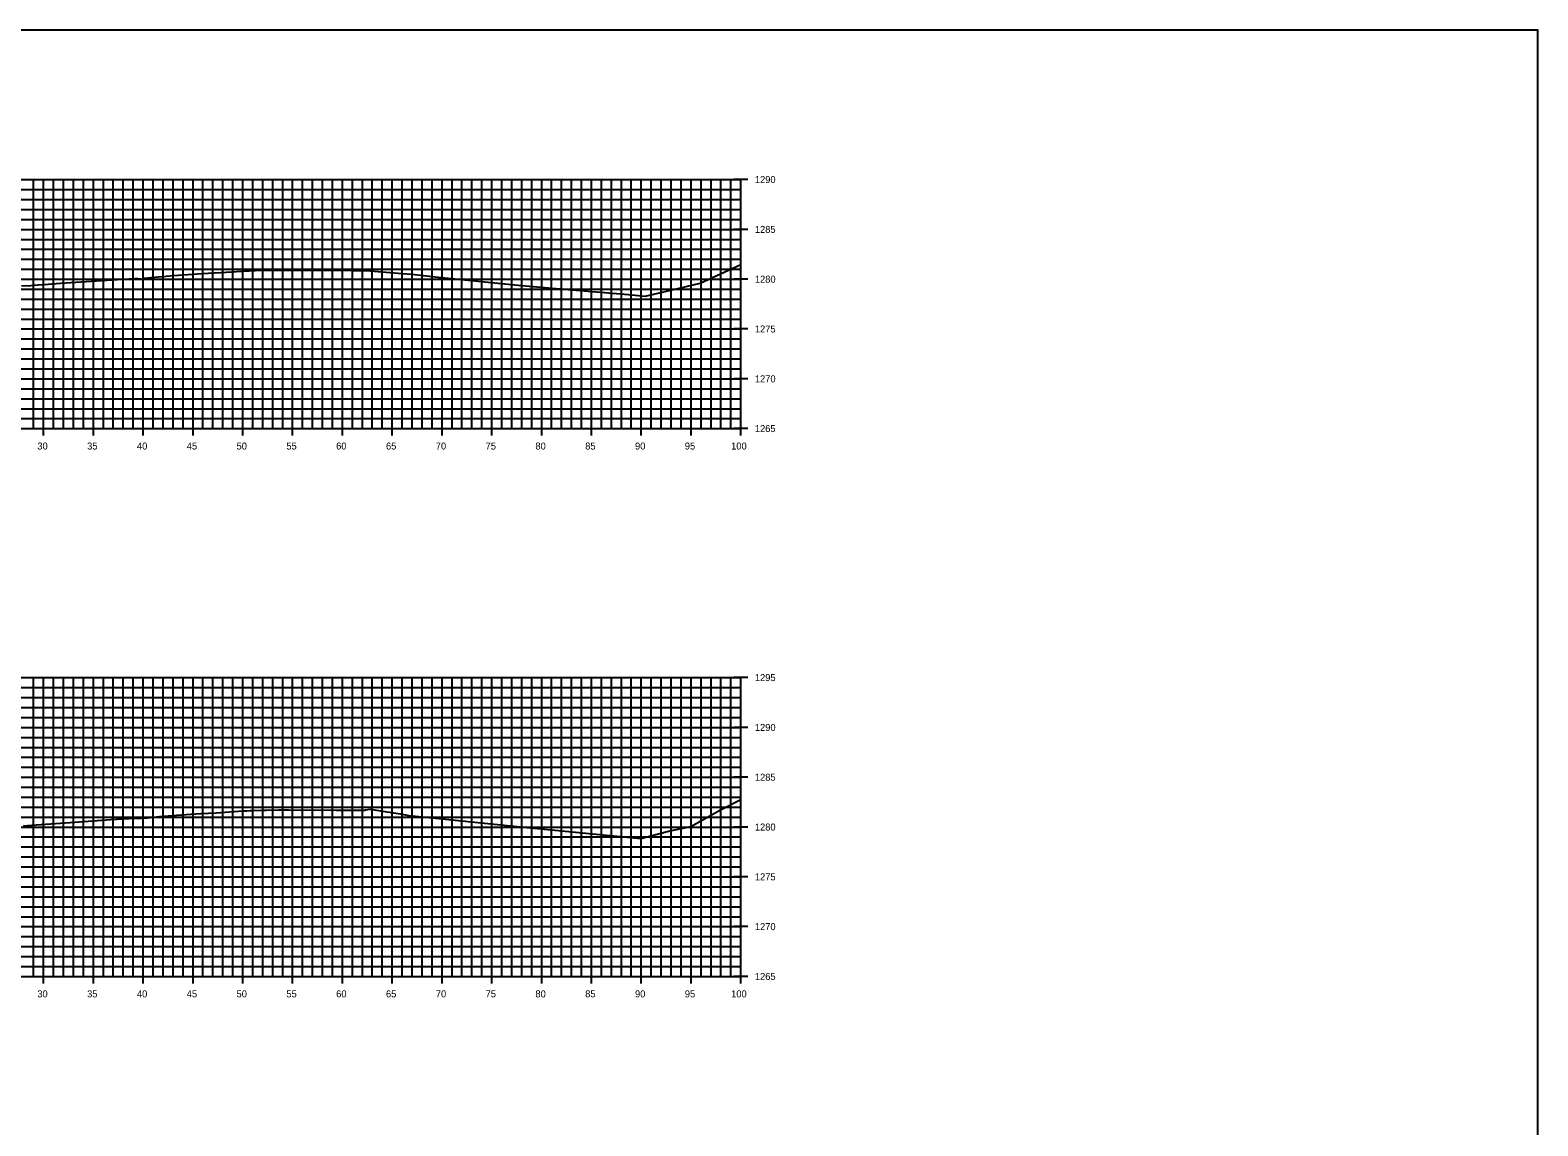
# Model space of a CAD drawing. Extents: x 674939 to 678919, y 750652 to 765176.
# Drawn here: x 678767.2 to 678918.5, y 756092.6 to 756202.6 of the extents above; entities that cross this region are included whole.
import ezdxf

# ---------------------------------------------------------------- set-up
doc = ezdxf.new("R2010")
doc.units = 0
for name, color, linetype in [('R_Axis', 7, 'Continuous'), ('R_Axis Annot', 7, 'Continuous'), ('R_Exist Surface', 7, 'Continuous'), ('R_Grid', 7, 'Continuous'), ('R_No Plot', 7, 'Continuous')]:
    doc.layers.add(name, color=color, linetype=linetype)

msp = doc.modelspace()

# ---------------------------------------------------------------- linework, layer by layer
at = {"layer": 'R_Axis'}
for p, q in [((678839.23, 756187.55), (678837.83, 756187.55)), ((678838.53, 756162.55), (678838.53, 756187.55)), ((678839.23, 756182.55), (678837.83, 756182.55)), ((678839.23, 756177.55), (678837.83, 756177.55)), ((678839.23, 756172.55), (678837.83, 756172.55)), ((678839.23, 756167.55), (678837.83, 756167.55)), ((678768.53, 756161.85), (678768.53, 756163.25)), ((678773.53, 756161.85), (678773.53, 756163.25)), ((678778.53, 756161.85), (678778.53, 756163.25)), ((678783.53, 756161.85), (678783.53, 756163.25)), ((678788.53, 756161.85), (678788.53, 756163.25)), ((678793.53, 756161.85), (678793.53, 756163.25)), ((678798.53, 756161.85), (678798.53, 756163.25)), ((678803.53, 756161.85), (678803.53, 756163.25)), ((678808.53, 756161.85), (678808.53, 756163.25)), ((678813.53, 756161.85), (678813.53, 756163.25)), ((678818.53, 756161.85), (678818.53, 756163.25)), ((678823.53, 756161.85), (678823.53, 756163.25)), ((678828.53, 756161.85), (678828.53, 756163.25)), ((678833.53, 756161.85), (678833.53, 756163.25)), ((678838.53, 756161.85), (678838.53, 756163.25)), ((678638.53, 756162.55), (678838.53, 756162.55)), ((678839.23, 756162.55), (678837.83, 756162.55)), ((678839.23, 756137.55), (678837.83, 756137.55)), ((678838.53, 756107.55), (678838.53, 756137.55)), ((678839.23, 756132.55), (678837.83, 756132.55)), ((678839.23, 756127.55), (678837.83, 756127.55)), ((678839.23, 756122.55), (678837.83, 756122.55)), ((678839.23, 756117.55), (678837.83, 756117.55)), ((678839.23, 756112.55), (678837.83, 756112.55)), ((678638.53, 756107.55), (678838.53, 756107.55)), ((678768.53, 756106.85), (678768.53, 756108.25)), ((678773.53, 756106.85), (678773.53, 756108.25)), ((678778.53, 756106.85), (678778.53, 756108.25)), ((678783.53, 756106.85), (678783.53, 756108.25)), ((678788.53, 756106.85), (678788.53, 756108.25)), ((678793.53, 756106.85), (678793.53, 756108.25)), ((678798.53, 756106.85), (678798.53, 756108.25)), ((678803.53, 756106.85), (678803.53, 756108.25)), ((678808.53, 756106.85), (678808.53, 756108.25)), ((678813.53, 756106.85), (678813.53, 756108.25)), ((678818.53, 756106.85), (678818.53, 756108.25)), ((678823.53, 756106.85), (678823.53, 756108.25)), ((678828.53, 756106.85), (678828.53, 756108.25)), ((678833.53, 756106.85), (678833.53, 756108.25)), ((678839.23, 756107.55), (678837.83, 756107.55)), ((678838.53, 756106.85), (678838.53, 756108.25))]:
    msp.add_line(p, q, dxfattribs=at)
at = {"layer": 'R_Exist Surface'}
for points in [[(678766.31, 756176.88), (678767.24, 756176.93), (678768, 756176.98), (678768.99, 756177.06), (678769.37, 756177.09), (678770.24, 756177.15), (678772.3, 756177.29), (678775.38, 756177.47), (678776.47, 756177.54), (678777.69, 756177.61), (678778, 756177.61), (678778.25, 756177.6), (678778.37, 756177.56), (678778.61, 756177.65), (678779.32, 756177.72), (678780.05, 756177.8), (678781.62, 756177.91), (678784.41, 756178.11), (678786.33, 756178.22), (678788.97, 756178.38), (678789.18, 756178.39), (678789.53, 756178.41), (678789.64, 756178.42), (678789.77, 756178.43), (678790.72, 756178.44), (678792.27, 756178.44), (678795.68, 756178.44), (678797.33, 756178.44), (678797.67, 756178.44), (678799.65, 756178.42), (678800.65, 756178.41), (678800.69, 756178.42), (678800.92, 756178.43), (678804.51, 756178.12), (678805.5, 756178.04), (678808.14, 756177.75), (678816.49, 756176.92), (678820, 756176.6), (678827.26, 756176.01), (678828.93, 756175.84), (678830.79, 756176.27), (678834.44, 756177.16), (678838.53, 756179.02)], [(678766.49, 756122.67), (678767.8, 756122.78), (678771.19, 756123.01), (678775.29, 756123.29), (678777.72, 756123.45), (678778.09, 756123.44), (678778.32, 756123.43), (678778.95, 756123.49), (678780.17, 756123.6), (678781.87, 756123.73), (678784.32, 756123.9), (678785.86, 756123.99), (678788.57, 756124.16), (678788.92, 756124.18), (678789.31, 756124.21), (678789.41, 756124.21), (678789.52, 756124.22), (678790.39, 756124.23), (678790.92, 756124.23), (678792.16, 756124.26), (678793.15, 756124.26), (678797.87, 756124.25), (678800.52, 756124.23), (678800.77, 756124.25), (678800.85, 756124.26), (678801.09, 756124.3), (678801.3, 756124.34), (678804.32, 756123.86), (678805.18, 756123.72), (678807.89, 756123.44), (678816.69, 756122.53), (678820.57, 756122.17), (678828.5, 756121.39), (678831.26, 756122.15), (678833.52, 756122.6), (678836.47, 756124.29), (678838.53, 756125.31)]]:
    msp.add_lwpolyline(points, dxfattribs=at)
at = {"layer": 'R_Grid'}
for p, q in [((678638.53, 756187.55), (678838.53, 756187.55)), ((678767.53, 756162.55), (678767.53, 756187.55)), ((678768.53, 756162.55), (678768.53, 756187.55)), ((678769.53, 756162.55), (678769.53, 756187.55)), ((678770.53, 756162.55), (678770.53, 756187.55)), ((678771.53, 756162.55), (678771.53, 756187.55)), ((678772.53, 756162.55), (678772.53, 756187.55)), ((678773.53, 756162.55), (678773.53, 756187.55)), ((678774.53, 756162.55), (678774.53, 756187.55)), ((678775.53, 756162.55), (678775.53, 756187.55)), ((678776.53, 756162.55), (678776.53, 756187.55)), ((678777.53, 756162.55), (678777.53, 756187.55)), ((678778.53, 756162.55), (678778.53, 756187.55)), ((678779.53, 756162.55), (678779.53, 756187.55)), ((678780.53, 756162.55), (678780.53, 756187.55)), ((678781.53, 756162.55), (678781.53, 756187.55)), ((678782.53, 756162.55), (678782.53, 756187.55)), ((678783.53, 756162.55), (678783.53, 756187.55)), ((678784.53, 756162.55), (678784.53, 756187.55)), ((678785.53, 756162.55), (678785.53, 756187.55)), ((678786.53, 756162.55), (678786.53, 756187.55)), ((678787.53, 756162.55), (678787.53, 756187.55)), ((678788.53, 756162.55), (678788.53, 756187.55)), ((678789.53, 756162.55), (678789.53, 756187.55)), ((678790.53, 756162.55), (678790.53, 756187.55)), ((678791.53, 756162.55), (678791.53, 756187.55)), ((678792.53, 756162.55), (678792.53, 756187.55)), ((678793.53, 756162.55), (678793.53, 756187.55)), ((678794.53, 756162.55), (678794.53, 756187.55)), ((678795.53, 756162.55), (678795.53, 756187.55)), ((678796.53, 756162.55), (678796.53, 756187.55)), ((678797.53, 756162.55), (678797.53, 756187.55)), ((678798.53, 756162.55), (678798.53, 756187.55)), ((678799.53, 756162.55), (678799.53, 756187.55)), ((678800.53, 756162.55), (678800.53, 756187.55)), ((678801.53, 756162.55), (678801.53, 756187.55)), ((678802.53, 756162.55), (678802.53, 756187.55)), ((678803.53, 756162.55), (678803.53, 756187.55)), ((678804.53, 756162.55), (678804.53, 756187.55)), ((678805.53, 756162.55), (678805.53, 756187.55)), ((678806.53, 756162.55), (678806.53, 756187.55)), ((678807.53, 756162.55), (678807.53, 756187.55)), ((678808.53, 756162.55), (678808.53, 756187.55)), ((678809.53, 756162.55), (678809.53, 756187.55)), ((678810.53, 756162.55), (678810.53, 756187.55)), ((678811.53, 756162.55), (678811.53, 756187.55)), ((678812.53, 756162.55), (678812.53, 756187.55)), ((678813.53, 756162.55), (678813.53, 756187.55)), ((678814.53, 756162.55), (678814.53, 756187.55)), ((678815.53, 756162.55), (678815.53, 756187.55)), ((678816.53, 756162.55), (678816.53, 756187.55)), ((678817.53, 756162.55), (678817.53, 756187.55)), ((678818.53, 756162.55), (678818.53, 756187.55)), ((678819.53, 756162.55), (678819.53, 756187.55)), ((678820.53, 756162.55), (678820.53, 756187.55)), ((678821.53, 756162.55), (678821.53, 756187.55)), ((678822.53, 756162.55), (678822.53, 756187.55)), ((678823.53, 756162.55), (678823.53, 756187.55)), ((678824.53, 756162.55), (678824.53, 756187.55)), ((678825.53, 756162.55), (678825.53, 756187.55)), ((678826.53, 756162.55), (678826.53, 756187.55)), ((678827.53, 756162.55), (678827.53, 756187.55)), ((678828.53, 756162.55), (678828.53, 756187.55)), ((678829.53, 756162.55), (678829.53, 756187.55)), ((678830.53, 756162.55), (678830.53, 756187.55)), ((678831.53, 756162.55), (678831.53, 756187.55)), ((678832.53, 756162.55), (678832.53, 756187.55)), ((678833.53, 756162.55), (678833.53, 756187.55)), ((678834.53, 756162.55), (678834.53, 756187.55)), ((678835.53, 756162.55), (678835.53, 756187.55)), ((678836.53, 756162.55), (678836.53, 756187.55)), ((678837.53, 756162.55), (678837.53, 756187.55)), ((678838.53, 756162.55), (678838.53, 756187.55)), ((678638.53, 756186.55), (678838.53, 756186.55)), ((678638.53, 756185.55), (678838.53, 756185.55)), ((678638.53, 756184.55), (678838.53, 756184.55)), ((678638.53, 756183.55), (678838.53, 756183.55)), ((678638.53, 756182.55), (678838.53, 756182.55)), ((678638.53, 756181.55), (678838.53, 756181.55)), ((678638.53, 756180.55), (678838.53, 756180.55)), ((678638.53, 756179.55), (678838.53, 756179.55)), ((678638.53, 756178.55), (678838.53, 756178.55)), ((678638.53, 756177.55), (678838.53, 756177.55)), ((678638.53, 756176.55), (678838.53, 756176.55)), ((678638.53, 756175.55), (678838.53, 756175.55)), ((678638.53, 756174.55), (678838.53, 756174.55)), ((678638.53, 756173.55), (678838.53, 756173.55)), ((678638.53, 756172.55), (678838.53, 756172.55)), ((678638.53, 756171.55), (678838.53, 756171.55)), ((678638.53, 756170.55), (678838.53, 756170.55)), ((678638.53, 756169.55), (678838.53, 756169.55)), ((678638.53, 756168.55), (678838.53, 756168.55)), ((678638.53, 756167.55), (678838.53, 756167.55)), ((678638.53, 756166.55), (678838.53, 756166.55)), ((678638.53, 756165.55), (678838.53, 756165.55)), ((678638.53, 756164.55), (678838.53, 756164.55)), ((678638.53, 756163.55), (678838.53, 756163.55)), ((678638.53, 756162.55), (678838.53, 756162.55)), ((678638.53, 756137.55), (678838.53, 756137.55)), ((678767.53, 756107.55), (678767.53, 756137.55)), ((678768.53, 756107.55), (678768.53, 756137.55)), ((678769.53, 756107.55), (678769.53, 756137.55)), ((678770.53, 756107.55), (678770.53, 756137.55)), ((678771.53, 756107.55), (678771.53, 756137.55)), ((678772.53, 756107.55), (678772.53, 756137.55)), ((678773.53, 756107.55), (678773.53, 756137.55)), ((678774.53, 756107.55), (678774.53, 756137.55)), ((678775.53, 756107.55), (678775.53, 756137.55)), ((678776.53, 756107.55), (678776.53, 756137.55)), ((678777.53, 756107.55), (678777.53, 756137.55)), ((678778.53, 756107.55), (678778.53, 756137.55)), ((678779.53, 756107.55), (678779.53, 756137.55)), ((678780.53, 756107.55), (678780.53, 756137.55)), ((678781.53, 756107.55), (678781.53, 756137.55)), ((678782.53, 756107.55), (678782.53, 756137.55)), ((678783.53, 756107.55), (678783.53, 756137.55)), ((678784.53, 756107.55), (678784.53, 756137.55)), ((678785.53, 756107.55), (678785.53, 756137.55)), ((678786.53, 756107.55), (678786.53, 756137.55)), ((678787.53, 756107.55), (678787.53, 756137.55)), ((678788.53, 756107.55), (678788.53, 756137.55)), ((678789.53, 756107.55), (678789.53, 756137.55)), ((678790.53, 756107.55), (678790.53, 756137.55)), ((678791.53, 756107.55), (678791.53, 756137.55)), ((678792.53, 756107.55), (678792.53, 756137.55)), ((678793.53, 756107.55), (678793.53, 756137.55)), ((678794.53, 756107.55), (678794.53, 756137.55)), ((678795.53, 756107.55), (678795.53, 756137.55)), ((678796.53, 756107.55), (678796.53, 756137.55)), ((678797.53, 756107.55), (678797.53, 756137.55)), ((678798.53, 756107.55), (678798.53, 756137.55)), ((678799.53, 756107.55), (678799.53, 756137.55)), ((678800.53, 756107.55), (678800.53, 756137.55)), ((678801.53, 756107.55), (678801.53, 756137.55)), ((678802.53, 756107.55), (678802.53, 756137.55)), ((678803.53, 756107.55), (678803.53, 756137.55)), ((678804.53, 756107.55), (678804.53, 756137.55)), ((678805.53, 756107.55), (678805.53, 756137.55)), ((678806.53, 756107.55), (678806.53, 756137.55)), ((678807.53, 756107.55), (678807.53, 756137.55)), ((678808.53, 756107.55), (678808.53, 756137.55)), ((678809.53, 756107.55), (678809.53, 756137.55)), ((678810.53, 756107.55), (678810.53, 756137.55)), ((678811.53, 756107.55), (678811.53, 756137.55)), ((678812.53, 756107.55), (678812.53, 756137.55)), ((678813.53, 756107.55), (678813.53, 756137.55)), ((678814.53, 756107.55), (678814.53, 756137.55)), ((678815.53, 756107.55), (678815.53, 756137.55)), ((678816.53, 756107.55), (678816.53, 756137.55)), ((678817.53, 756107.55), (678817.53, 756137.55)), ((678818.53, 756107.55), (678818.53, 756137.55)), ((678819.53, 756107.55), (678819.53, 756137.55)), ((678820.53, 756107.55), (678820.53, 756137.55)), ((678821.53, 756107.55), (678821.53, 756137.55)), ((678822.53, 756107.55), (678822.53, 756137.55)), ((678823.53, 756107.55), (678823.53, 756137.55)), ((678824.53, 756107.55), (678824.53, 756137.55)), ((678825.53, 756107.55), (678825.53, 756137.55)), ((678826.53, 756107.55), (678826.53, 756137.55)), ((678827.53, 756107.55), (678827.53, 756137.55)), ((678828.53, 756107.55), (678828.53, 756137.55)), ((678829.53, 756107.55), (678829.53, 756137.55)), ((678830.53, 756107.55), (678830.53, 756137.55)), ((678831.53, 756107.55), (678831.53, 756137.55)), ((678832.53, 756107.55), (678832.53, 756137.55)), ((678833.53, 756107.55), (678833.53, 756137.55)), ((678834.53, 756107.55), (678834.53, 756137.55)), ((678835.53, 756107.55), (678835.53, 756137.55)), ((678836.53, 756107.55), (678836.53, 756137.55)), ((678837.53, 756107.55), (678837.53, 756137.55)), ((678838.53, 756107.55), (678838.53, 756137.55)), ((678638.53, 756136.55), (678838.53, 756136.55)), ((678638.53, 756135.55), (678838.53, 756135.55)), ((678638.53, 756134.55), (678838.53, 756134.55)), ((678638.53, 756133.55), (678838.53, 756133.55)), ((678638.53, 756132.55), (678838.53, 756132.55)), ((678638.53, 756131.55), (678838.53, 756131.55)), ((678638.53, 756130.55), (678838.53, 756130.55)), ((678638.53, 756129.55), (678838.53, 756129.55)), ((678638.53, 756128.55), (678838.53, 756128.55)), ((678638.53, 756127.55), (678838.53, 756127.55)), ((678638.53, 756126.55), (678838.53, 756126.55)), ((678638.53, 756125.55), (678838.53, 756125.55)), ((678638.53, 756124.55), (678838.53, 756124.55)), ((678638.53, 756123.55), (678838.53, 756123.55)), ((678638.53, 756122.55), (678838.53, 756122.55)), ((678638.53, 756121.55), (678838.53, 756121.55)), ((678638.53, 756120.55), (678838.53, 756120.55)), ((678638.53, 756119.55), (678838.53, 756119.55)), ((678638.53, 756118.55), (678838.53, 756118.55)), ((678638.53, 756117.55), (678838.53, 756117.55)), ((678638.53, 756116.55), (678838.53, 756116.55)), ((678638.53, 756115.55), (678838.53, 756115.55)), ((678638.53, 756114.55), (678838.53, 756114.55)), ((678638.53, 756113.55), (678838.53, 756113.55)), ((678638.53, 756112.55), (678838.53, 756112.55)), ((678638.53, 756111.55), (678838.53, 756111.55)), ((678638.53, 756110.55), (678838.53, 756110.55)), ((678638.53, 756109.55), (678838.53, 756109.55)), ((678638.53, 756108.55), (678838.53, 756108.55)), ((678638.53, 756107.55), (678838.53, 756107.55))]:
    msp.add_line(p, q, dxfattribs=at)
at = {"layer": 'R_No Plot'}
msp.add_lwpolyline([(678578.53, 755982.55), (678918.53, 755982.55), (678918.53, 756202.55), (678578.53, 756202.55)], close=True, dxfattribs=at)

# ---------------------------------------------------------------- texts
at = {"layer": 'R_Axis Annot'}
for s, p in [('1290', (678839.93, 756187.2)), ('1285', (678839.93, 756182.2)), ('1280', (678839.93, 756177.2)), ('1275', (678839.93, 756172.2)), ('1270', (678839.93, 756167.2)), ('1265', (678839.93, 756162.2)), ('30', (678767.9, 756160.45)), ('35', (678772.9, 756160.45)), ('40', (678777.9, 756160.45)), ('45', (678782.9, 756160.45)), ('50', (678787.9, 756160.45)), ('55', (678792.9, 756160.45)), ('60', (678797.9, 756160.45)), ('65', (678802.9, 756160.45)), ('70', (678807.9, 756160.45)), ('75', (678812.9, 756160.45)), ('80', (678817.9, 756160.45)), ('85', (678822.9, 756160.45)), ('90', (678827.9, 756160.45)), ('95', (678832.9, 756160.45)), ('100', (678837.55, 756160.45)), ('1295', (678839.93, 756137.2)), ('1290', (678839.93, 756132.2)), ('1285', (678839.93, 756127.2)), ('1280', (678839.93, 756122.2)), ('1275', (678839.93, 756117.2)), ('1270', (678839.93, 756112.2)), ('1265', (678839.93, 756107.2)), ('30', (678767.9, 756105.45)), ('35', (678772.9, 756105.45)), ('40', (678777.9, 756105.45)), ('45', (678782.9, 756105.45)), ('50', (678787.9, 756105.45)), ('55', (678792.9, 756105.45)), ('60', (678797.9, 756105.45)), ('65', (678802.9, 756105.45)), ('70', (678807.9, 756105.45)), ('75', (678812.9, 756105.45)), ('80', (678817.9, 756105.45)), ('85', (678822.9, 756105.45)), ('90', (678827.9, 756105.45)), ('95', (678832.9, 756105.45)), ('100', (678837.55, 756105.45))]:
    msp.add_text(s, height=0.7, dxfattribs=at).set_placement(p)

doc.saveas('drawing.dxf')
